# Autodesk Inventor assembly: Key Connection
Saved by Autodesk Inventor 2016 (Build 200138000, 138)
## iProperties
Created: 2015-08
Part Number: Key Connection
Document SubType Name: Assembly
Designer: stank
ClientObjectVersion: 1
Author: stank
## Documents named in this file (2)
- E:\Turbokompr\Sklop turbokompresora\Design Accelerator\Key Connection5.iam
- C:\Users\stank\Documents\Inventor\Content Center Files\R2016\en-US\ISO 2491 - A\ISO 2491 - A  8 x 5 x 20.ipt
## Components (1 placed, 1 different names)
1. ISO 2491 A A  8 x 5 x 20:1
